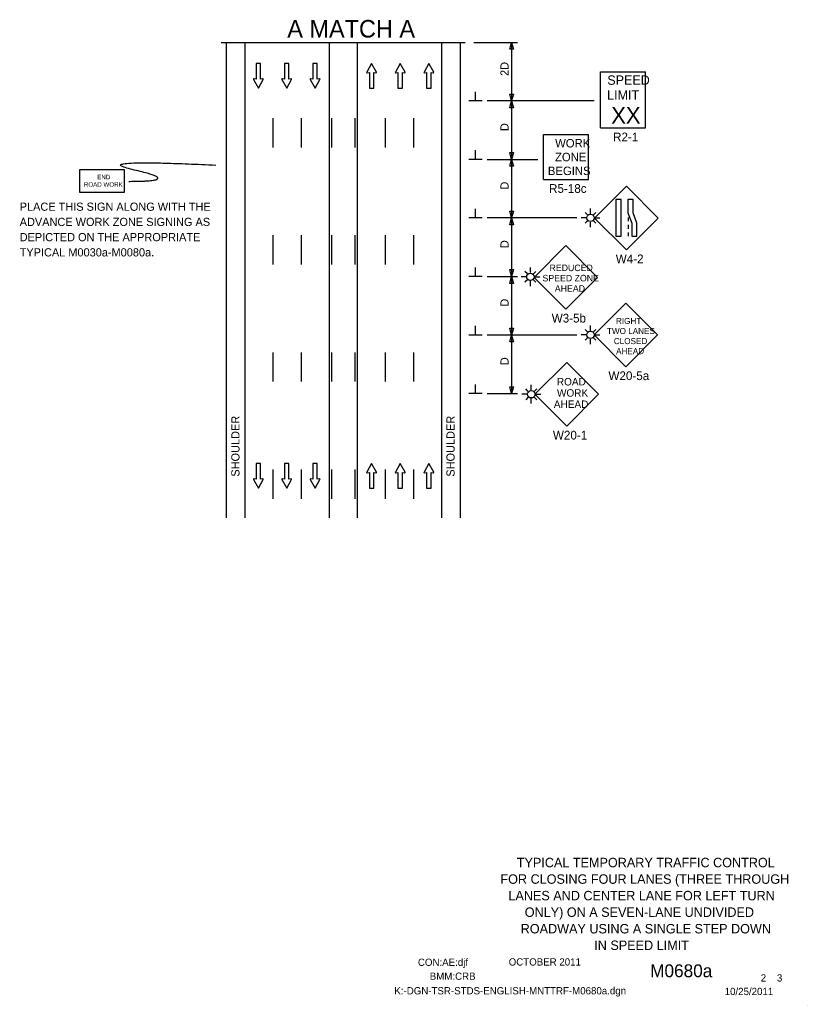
# Model space of a CAD drawing. Extents: x 16038 to 19504, y 5710 to 8321.
# Drawn here: x 17779 to 18453, y 5924 to 6766 of the extents above; entities that cross this region are included whole.
import ezdxf

# ---------------------------------------------------------------- set-up
doc = ezdxf.new("R2010")
doc.units = 0
for name, color, linetype in [('ALI_LEGAL_EX', 7, 'Continuous'), ('BORDER', 7, 'Continuous'), ('BORDER_SIGNAL_WO', 7, 'Continuous'), ('MT_SCRATCH_LEVEL_E', 7, 'Continuous'), ('PAVT_EDGE_EX', 7, 'Continuous'), ('TRAFFIC_SIGNS_PR', 7, 'Continuous'), ('TYPICAL_TEXT_DIMEN_PR', 7, 'Continuous')]:
    doc.layers.add(name, color=color, linetype=linetype)

msp = doc.modelspace()

# ---------------------------------------------------------------- linework, layer by layer
at = {"layer": 'ALI_LEGAL_EX'}
for points in [[(17995.77, 6682.18), (17995.77, 6657.18)], [(18019.77, 6682.18), (18019.77, 6657.18)], [(18045.77, 6682.18), (18045.77, 6657.18)], [(18065.77, 6682.18), (18065.77, 6657.18)], [(18091.77, 6682.18), (18091.77, 6657.18)], [(18115.77, 6682.18), (18115.77, 6657.18)], [(17995.77, 6582.18), (17995.77, 6557.18)], [(18019.77, 6582.18), (18019.77, 6557.18)], [(18045.77, 6582.18), (18045.77, 6557.18)], [(18065.77, 6582.18), (18065.77, 6557.18)], [(18091.77, 6582.18), (18091.77, 6557.18)], [(18115.77, 6582.18), (18115.77, 6557.18)], [(17995.77, 6482.18), (17995.77, 6457.18)], [(18019.77, 6482.18), (18019.77, 6457.18)], [(18045.77, 6482.18), (18045.77, 6457.18)], [(18065.77, 6482.18), (18065.77, 6457.18)], [(18091.77, 6482.18), (18091.77, 6457.18)], [(18115.77, 6482.18), (18115.77, 6457.18)], [(17995.77, 6382.18), (17995.77, 6357.18)], [(18019.77, 6382.18), (18019.77, 6357.18)], [(18045.77, 6382.18), (18045.77, 6357.18)], [(18065.77, 6382.18), (18065.77, 6357.18)], [(18091.77, 6382.18), (18091.77, 6357.18)], [(18115.77, 6382.18), (18115.77, 6357.18)]]:
    msp.add_lwpolyline(points, dxfattribs=at)
at = {"layer": 'BORDER'}
for p, q in [((18318.25, 6011.25), (18318.25, 6011.25)), ((18452.55, 5924.4), (18452.55, 5924.4))]:
    msp.add_line(p, q, dxfattribs=at)
at = {"layer": 'MT_SCRATCH_LEVEL_E'}
for p, q in [((17985.18, 6728.89), (17981.44, 6728.89)), ((17981.44, 6728.89), (17981.44, 6715.63)), ((17985.18, 6728.89), (17981.44, 6728.89)), ((17981.44, 6728.89), (17981.44, 6715.63)), ((17985.18, 6715.63), (17985.18, 6728.89)), ((17985.18, 6715.63), (17985.18, 6728.89)), ((18009.44, 6728.89), (18005.69, 6728.89)), ((18005.69, 6728.89), (18005.69, 6715.63)), ((18009.44, 6728.89), (18005.69, 6728.89)), ((18005.69, 6728.89), (18005.69, 6715.63)), ((18009.44, 6715.63), (18009.44, 6728.89)), ((18009.44, 6715.63), (18009.44, 6728.89)), ((18033.69, 6728.89), (18029.95, 6728.89)), ((18029.95, 6728.89), (18029.95, 6715.63)), ((18033.69, 6728.89), (18029.95, 6728.89)), ((18029.95, 6728.89), (18029.95, 6715.63)), ((18033.69, 6715.63), (18033.69, 6728.89)), ((18033.69, 6715.63), (18033.69, 6728.89)), ((18080.01, 6728.89), (18075.9, 6721.65)), ((18080.01, 6728.89), (18075.9, 6721.65)), ((18084.16, 6721.65), (18080.01, 6728.89)), ((18084.16, 6721.65), (18080.01, 6728.89)), ((18104.51, 6728.89), (18100.4, 6721.65)), ((18104.51, 6728.89), (18100.4, 6721.65)), ((18108.65, 6721.65), (18104.51, 6728.89)), ((18108.65, 6721.65), (18104.51, 6728.89)), ((18129, 6728.89), (18124.89, 6721.65)), ((18129, 6728.89), (18124.89, 6721.65)), ((18133.15, 6721.65), (18129, 6728.89)), ((18133.15, 6721.65), (18129, 6728.89)), ((18076.38, 6720.96), (18078.16, 6721.28)), ((18076.38, 6720.96), (18078.16, 6721.28)), ((18078.16, 6721.28), (18078.16, 6708.02)), ((18078.16, 6721.28), (18078.16, 6708.02)), ((18081.9, 6708.02), (18081.9, 6721.28)), ((18081.9, 6721.28), (18083.68, 6720.96)), ((18081.9, 6708.02), (18081.9, 6721.28)), ((18081.9, 6721.28), (18083.68, 6720.96)), ((18100.88, 6720.96), (18102.65, 6721.28)), ((18100.88, 6720.96), (18102.65, 6721.28)), ((18102.65, 6721.28), (18102.65, 6708.02)), ((18102.65, 6721.28), (18102.65, 6708.02)), ((18106.4, 6708.02), (18106.4, 6721.28)), ((18106.4, 6721.28), (18108.17, 6720.96)), ((18106.4, 6708.02), (18106.4, 6721.28)), ((18106.4, 6721.28), (18108.17, 6720.96)), ((18125.37, 6720.96), (18127.15, 6721.28)), ((18125.37, 6720.96), (18127.15, 6721.28)), ((18127.15, 6721.28), (18127.15, 6708.02)), ((18127.15, 6721.28), (18127.15, 6708.02)), ((18130.89, 6708.02), (18130.89, 6721.28)), ((18130.89, 6721.28), (18132.67, 6720.96)), ((18130.89, 6708.02), (18130.89, 6721.28)), ((18130.89, 6721.28), (18132.67, 6720.96)), ((17979.18, 6715.26), (17983.33, 6708.02)), ((17979.18, 6715.26), (17983.33, 6708.02)), ((17981.44, 6715.63), (17979.66, 6715.95)), ((17981.44, 6715.63), (17979.66, 6715.95)), ((17983.33, 6708.02), (17987.44, 6715.26)), ((17983.33, 6708.02), (17987.44, 6715.26)), ((17986.96, 6715.95), (17985.18, 6715.63)), ((17986.96, 6715.95), (17985.18, 6715.63)), ((18003.44, 6715.26), (18007.58, 6708.02)), ((18003.44, 6715.26), (18007.58, 6708.02)), ((18005.69, 6715.63), (18003.92, 6715.95)), ((18005.69, 6715.63), (18003.92, 6715.95)), ((18007.58, 6708.02), (18011.69, 6715.26)), ((18007.58, 6708.02), (18011.69, 6715.26)), ((18011.21, 6715.95), (18009.44, 6715.63)), ((18011.21, 6715.95), (18009.44, 6715.63)), ((18027.69, 6715.26), (18031.84, 6708.02)), ((18027.69, 6715.26), (18031.84, 6708.02)), ((18029.95, 6715.63), (18028.17, 6715.95)), ((18029.95, 6715.63), (18028.17, 6715.95)), ((18031.84, 6708.02), (18035.95, 6715.26)), ((18031.84, 6708.02), (18035.95, 6715.26)), ((18035.47, 6715.95), (18033.69, 6715.63)), ((18035.47, 6715.95), (18033.69, 6715.63)), ((18078.16, 6708.02), (18081.9, 6708.02)), ((18078.16, 6708.02), (18081.9, 6708.02)), ((18102.65, 6708.02), (18106.4, 6708.02)), ((18102.65, 6708.02), (18106.4, 6708.02)), ((18127.15, 6708.02), (18130.89, 6708.02)), ((18127.15, 6708.02), (18130.89, 6708.02)), ((17985.18, 6387.14), (17981.44, 6387.14)), ((17981.44, 6387.14), (17981.44, 6373.88)), ((17985.18, 6387.14), (17981.44, 6387.14)), ((17981.44, 6387.14), (17981.44, 6373.88)), ((17985.18, 6373.88), (17985.18, 6387.14)), ((17985.18, 6373.88), (17985.18, 6387.14)), ((18009.44, 6387.14), (18005.69, 6387.14)), ((18005.69, 6387.14), (18005.69, 6373.88)), ((18009.44, 6387.14), (18005.69, 6387.14)), ((18005.69, 6387.14), (18005.69, 6373.88)), ((18009.44, 6373.88), (18009.44, 6387.14)), ((18009.44, 6373.88), (18009.44, 6387.14)), ((18033.69, 6387.14), (18029.95, 6387.14)), ((18029.95, 6387.14), (18029.95, 6373.88)), ((18033.69, 6387.14), (18029.95, 6387.14)), ((18029.95, 6387.14), (18029.95, 6373.88)), ((18033.69, 6373.88), (18033.69, 6387.14)), ((18033.69, 6373.88), (18033.69, 6387.14)), ((18080.01, 6387.14), (18075.9, 6379.9)), ((18080.01, 6387.14), (18075.9, 6379.9)), ((18084.16, 6379.9), (18080.01, 6387.14)), ((18084.16, 6379.9), (18080.01, 6387.14)), ((18104.51, 6387.14), (18100.4, 6379.9)), ((18104.51, 6387.14), (18100.4, 6379.9)), ((18108.65, 6379.9), (18104.51, 6387.14)), ((18108.65, 6379.9), (18104.51, 6387.14)), ((18129, 6387.14), (18124.89, 6379.9)), ((18129, 6387.14), (18124.89, 6379.9)), ((18133.15, 6379.9), (18129, 6387.14)), ((18133.15, 6379.9), (18129, 6387.14)), ((17981.44, 6373.88), (17979.66, 6374.2)), ((17981.44, 6373.88), (17979.66, 6374.2)), ((17986.96, 6374.2), (17985.18, 6373.88)), ((17986.96, 6374.2), (17985.18, 6373.88)), ((18005.69, 6373.88), (18003.92, 6374.2)), ((18005.69, 6373.88), (18003.92, 6374.2)), ((18011.21, 6374.2), (18009.44, 6373.88)), ((18011.21, 6374.2), (18009.44, 6373.88)), ((18029.95, 6373.88), (18028.17, 6374.2)), ((18029.95, 6373.88), (18028.17, 6374.2)), ((18035.47, 6374.2), (18033.69, 6373.88)), ((18035.47, 6374.2), (18033.69, 6373.88)), ((18076.38, 6379.22), (18078.16, 6379.53)), ((18076.38, 6379.22), (18078.16, 6379.53)), ((18078.16, 6379.53), (18078.16, 6366.27)), ((18078.16, 6379.53), (18078.16, 6366.27)), ((18081.9, 6366.27), (18081.9, 6379.53)), ((18081.9, 6379.53), (18083.68, 6379.22)), ((18081.9, 6366.27), (18081.9, 6379.53)), ((18081.9, 6379.53), (18083.68, 6379.22)), ((18100.88, 6379.22), (18102.65, 6379.53)), ((18100.88, 6379.22), (18102.65, 6379.53)), ((18102.65, 6379.53), (18102.65, 6366.27)), ((18102.65, 6379.53), (18102.65, 6366.27)), ((18106.4, 6366.27), (18106.4, 6379.53)), ((18106.4, 6379.53), (18108.17, 6379.22)), ((18106.4, 6366.27), (18106.4, 6379.53)), ((18106.4, 6379.53), (18108.17, 6379.22)), ((18125.37, 6379.22), (18127.15, 6379.53)), ((18125.37, 6379.22), (18127.15, 6379.53)), ((18127.15, 6379.53), (18127.15, 6366.27)), ((18127.15, 6379.53), (18127.15, 6366.27)), ((18130.89, 6366.27), (18130.89, 6379.53)), ((18130.89, 6379.53), (18132.67, 6379.22)), ((18130.89, 6366.27), (18130.89, 6379.53)), ((18130.89, 6379.53), (18132.67, 6379.22)), ((17979.18, 6373.51), (17983.33, 6366.27)), ((17979.18, 6373.51), (17983.33, 6366.27)), ((17983.33, 6366.27), (17987.44, 6373.51)), ((17983.33, 6366.27), (17987.44, 6373.51)), ((18003.44, 6373.51), (18007.58, 6366.27)), ((18003.44, 6373.51), (18007.58, 6366.27)), ((18007.58, 6366.27), (18011.69, 6373.51)), ((18007.58, 6366.27), (18011.69, 6373.51)), ((18027.69, 6373.51), (18031.84, 6366.27)), ((18027.69, 6373.51), (18031.84, 6366.27)), ((18031.84, 6366.27), (18035.95, 6373.51)), ((18031.84, 6366.27), (18035.95, 6373.51)), ((18078.16, 6366.27), (18081.9, 6366.27)), ((18078.16, 6366.27), (18081.9, 6366.27)), ((18102.65, 6366.27), (18106.4, 6366.27)), ((18102.65, 6366.27), (18106.4, 6366.27)), ((18127.15, 6366.27), (18130.89, 6366.27)), ((18127.15, 6366.27), (18130.89, 6366.27))]:
    msp.add_line(p, q, dxfattribs=at)
for centre, start, end in [((18076.31, 6721.42), 150.42484, 279.96381), ((18076.31, 6721.42), 150.42484, 279.96381), ((18083.75, 6721.42), 260.03619, 29.77312), ((18083.75, 6721.42), 260.03619, 29.77312), ((18100.8, 6721.42), 150.42484, 279.96381), ((18100.8, 6721.42), 150.42484, 279.96381), ((18108.24, 6721.42), 260.03619, 29.77312), ((18108.24, 6721.42), 260.03619, 29.77312), ((18125.3, 6721.42), 150.42484, 279.96381), ((18125.3, 6721.42), 150.42484, 279.96381), ((18132.74, 6721.42), 260.03619, 29.77312), ((18132.74, 6721.42), 260.03619, 29.77312), ((17979.59, 6715.49), 80.03619, 209.77312), ((17979.59, 6715.49), 80.03619, 209.77312), ((17987.03, 6715.49), 330.42484, 99.96381), ((17987.03, 6715.49), 330.42484, 99.96381), ((18003.85, 6715.49), 80.03619, 209.77312), ((18003.85, 6715.49), 80.03619, 209.77312), ((18011.29, 6715.49), 330.42484, 99.96381), ((18011.29, 6715.49), 330.42484, 99.96381), ((18028.1, 6715.49), 80.03619, 209.77312), ((18028.1, 6715.49), 80.03619, 209.77312), ((18035.54, 6715.49), 330.42484, 99.96381), ((18035.54, 6715.49), 330.42484, 99.96381), ((17979.59, 6373.74), 80.03619, 209.77312), ((17979.59, 6373.74), 80.03619, 209.77312), ((17987.03, 6373.74), 330.42484, 99.96381), ((17987.03, 6373.74), 330.42484, 99.96381), ((18003.85, 6373.74), 80.03619, 209.77312), ((18003.85, 6373.74), 80.03619, 209.77312), ((18011.29, 6373.74), 330.42484, 99.96381), ((18011.29, 6373.74), 330.42484, 99.96381), ((18028.1, 6373.74), 80.03619, 209.77312), ((18028.1, 6373.74), 80.03619, 209.77312), ((18035.54, 6373.74), 330.42484, 99.96381), ((18035.54, 6373.74), 330.42484, 99.96381), ((18076.31, 6379.67), 150.42484, 279.96381), ((18076.31, 6379.67), 150.42484, 279.96381), ((18083.75, 6379.67), 260.03619, 29.77312), ((18083.75, 6379.67), 260.03619, 29.77312), ((18100.8, 6379.67), 150.42484, 279.96381), ((18100.8, 6379.67), 150.42484, 279.96381), ((18108.24, 6379.67), 260.03619, 29.77312), ((18108.24, 6379.67), 260.03619, 29.77312), ((18125.3, 6379.67), 150.42484, 279.96381), ((18125.3, 6379.67), 150.42484, 279.96381), ((18132.74, 6379.67), 260.03619, 29.77312), ((18132.74, 6379.67), 260.03619, 29.77312)]:
    msp.add_arc(centre, 0.463, start, end, dxfattribs=at)
at = {"layer": 'PAVT_EDGE_EX'}
for p, q in [((17955.77, 6747.01), (17955.77, 6340.84)), ((17971.77, 6747.01), (17971.77, 6340.84)), ((18043.77, 6747.01), (18043.77, 6340.84)), ((18067.77, 6747.01), (18067.77, 6340.84)), ((18139.77, 6747.01), (18139.77, 6340.84)), ((18155.77, 6747.01), (18155.77, 6340.84))]:
    msp.add_line(p, q, dxfattribs=at)
at = {"layer": 'TRAFFIC_SIGNS_PR'}
for p, q in [((18275.83, 6721.93), (18314.23, 6721.93)), ((18275.83, 6673.93), (18275.83, 6721.93)), ((18314.23, 6673.93), (18314.23, 6721.93)), ((18275.83, 6673.93), (18314.23, 6673.93)), ((18226.99, 6629.9), (18226.99, 6668.3)), ((18226.99, 6668.3), (18265.39, 6668.3)), ((18265.39, 6629.9), (18265.39, 6668.3)), ((18226.99, 6629.9), (18265.39, 6629.9)), ((18297.85, 6624.09), (18270.69, 6596.94)), ((18325, 6596.94), (18297.85, 6624.09)), ((18264.62, 6599.58), (18262.52, 6601.69)), ((18267.14, 6600.62), (18267.14, 6605.12)), ((18269.65, 6599.58), (18271.76, 6601.69)), ((18263.98, 6597.06), (18259.15, 6597.06)), ((18264.62, 6594.55), (18262.52, 6592.44)), ((18267.14, 6589.1), (18267.14, 6593.51)), ((18269.65, 6594.55), (18271.76, 6592.44)), ((18270.29, 6597.06), (18275.17, 6597.06)), ((18270.69, 6596.94), (18297.85, 6569.78)), ((18297.85, 6569.78), (18325, 6596.94)), ((18299.49, 6597.43), (18299.49, 6594.23)), ((18299.49, 6591.03), (18299.49, 6587.83)), ((18299.49, 6584.63), (18299.49, 6581.43)), ((18246.11, 6573.44), (18218.96, 6546.29)), ((18273.26, 6546.29), (18246.11, 6573.44)), ((18213.32, 6549.27), (18211.21, 6551.37)), ((18215.83, 6550.31), (18215.83, 6554.81)), ((18218.35, 6549.27), (18220.45, 6551.37)), ((18212.68, 6546.75), (18207.84, 6546.75)), ((18213.32, 6544.24), (18211.21, 6542.13)), ((18215.83, 6538.79), (18215.83, 6543.2)), ((18218.35, 6544.24), (18220.45, 6542.13)), ((18218.96, 6546.29), (18246.11, 6519.13)), ((18218.99, 6546.75), (18223.87, 6546.75)), ((18246.11, 6519.13), (18273.26, 6546.29)), ((18297.44, 6524.24), (18270.29, 6497.09)), ((18324.6, 6497.09), (18297.44, 6524.24)), ((18264.62, 6499.61), (18262.52, 6501.71)), ((18267.14, 6500.65), (18267.14, 6505.15)), ((18269.65, 6499.61), (18271.76, 6501.71)), ((18263.98, 6497.09), (18259.15, 6497.09)), ((18264.62, 6494.58), (18262.52, 6492.47)), ((18267.14, 6489.13), (18267.14, 6493.54)), ((18269.65, 6494.58), (18271.76, 6492.47)), ((18270.29, 6497.09), (18275.17, 6497.09)), ((18270.29, 6497.09), (18297.44, 6469.94)), ((18297.44, 6469.94), (18324.6, 6497.09)), ((18246.93, 6473.55), (18219.74, 6446.37)), ((18274.11, 6446.37), (18246.93, 6473.55)), ((18214.07, 6448.88), (18211.97, 6450.99)), ((18216.59, 6449.92), (18216.59, 6454.42)), ((18219.1, 6448.88), (18221.21, 6450.99)), ((18213.43, 6446.37), (18208.6, 6446.37)), ((18214.07, 6443.86), (18211.97, 6441.75)), ((18216.59, 6438.4), (18216.59, 6442.81)), ((18219.1, 6443.86), (18221.21, 6441.75)), ((18219.74, 6446.37), (18224.62, 6446.37)), ((18219.74, 6446.37), (18246.93, 6419.18)), ((18246.93, 6419.18), (18274.11, 6446.37))]:
    msp.add_line(p, q, dxfattribs=at)
for points in [[(17830.52, 6618.92), (17868.92, 6618.92), (17868.92, 6638.12), (17830.52, 6638.12)], [(18288.95, 6612.67), (18288.95, 6581.43), (18293.44, 6581.43), (18293.44, 6612.67)], [(18299.09, 6612.67), (18299.09, 6601.49), (18302.43, 6592.61), (18302.43, 6581.43), (18306.92, 6581.43), (18306.92, 6592.61), (18303.58, 6601.49), (18303.58, 6612.67)]]:
    msp.add_lwpolyline(points, close=True, dxfattribs=at)
for centre in [(18267.14, 6597.06), (18215.83, 6546.75), (18267.14, 6497.09), (18216.59, 6446.37)]:
    msp.add_circle(centre, 3.15, dxfattribs=at)
msp.add_open_spline([(17872.52, 6628.3), (17919.75, 6628.3), (17834.73, 6647.64), (17947.03, 6642.15)], degree=2, dxfattribs=at)
at = {"layer": 'TYPICAL_TEXT_DIMEN_PR'}
for p, q in [((17951.47, 6747.01), (18160.07, 6747.01)), ((18043.77, 6747.01), (18067.77, 6747.01)), ((18167.46, 6747.01), (18204.77, 6747.01)), ((18198.2, 6741.15), (18199.77, 6747.01)), ((18199.77, 6747.01), (18201.34, 6741.15)), ((18199.77, 6747.01), (18199.77, 6697.01)), ((18199.77, 6741.15), (18198.2, 6741.15)), ((18201.34, 6741.15), (18199.77, 6741.15)), ((18168.89, 6697.01), (18168.89, 6704.79)), ((18199.77, 6697.01), (18198.2, 6702.87)), ((18198.2, 6702.87), (18199.77, 6702.87)), ((18199.77, 6702.87), (18201.34, 6702.87)), ((18201.34, 6702.87), (18199.77, 6697.01)), ((18174.52, 6697.01), (18163.27, 6697.01)), ((18270.46, 6697.01), (18178.77, 6697.01)), ((18198.2, 6691.15), (18199.77, 6697.01)), ((18199.77, 6697.01), (18201.34, 6691.15)), ((18199.77, 6697.01), (18199.77, 6647.01)), ((18199.77, 6691.15), (18198.2, 6691.15)), ((18201.34, 6691.15), (18199.77, 6691.15)), ((18168.89, 6647.01), (18168.89, 6654.79)), ((18199.77, 6647.01), (18198.2, 6652.87)), ((18198.2, 6652.87), (18199.77, 6652.87)), ((18199.77, 6652.87), (18201.34, 6652.87)), ((18201.34, 6652.87), (18199.77, 6647.01)), ((18174.52, 6647.01), (18163.27, 6647.01)), ((18178.77, 6647.01), (18222.27, 6647.01)), ((18198.2, 6641.15), (18199.77, 6647.01)), ((18199.77, 6647.01), (18199.77, 6597.01)), ((18199.77, 6647.01), (18201.34, 6641.15)), ((18199.77, 6641.15), (18198.2, 6641.15)), ((18201.34, 6641.15), (18199.77, 6641.15)), ((18168.89, 6597.01), (18168.89, 6604.79)), ((18199.77, 6597.01), (18198.2, 6602.87)), ((18198.2, 6602.87), (18199.77, 6602.87)), ((18199.77, 6602.87), (18201.34, 6602.87)), ((18201.34, 6602.87), (18199.77, 6597.01)), ((18174.52, 6597.01), (18163.27, 6597.01)), ((18255.57, 6597.01), (18178.77, 6597.01)), ((18198.2, 6591.15), (18199.77, 6597.01)), ((18199.77, 6597.01), (18201.34, 6591.15)), ((18199.77, 6597.01), (18199.77, 6547.01)), ((18199.77, 6591.15), (18198.2, 6591.15)), ((18201.34, 6591.15), (18199.77, 6591.15)), ((18168.89, 6547.01), (18168.89, 6554.79)), ((18199.77, 6547.01), (18198.2, 6552.87)), ((18198.2, 6552.87), (18199.77, 6552.87)), ((18199.77, 6552.87), (18201.34, 6552.87)), ((18201.34, 6552.87), (18199.77, 6547.01)), ((18174.52, 6547.01), (18163.27, 6547.01)), ((18178.77, 6547.01), (18204.77, 6547.01)), ((18198.2, 6541.15), (18199.77, 6547.01)), ((18199.77, 6547.01), (18201.34, 6541.15)), ((18199.77, 6547.01), (18199.77, 6497.01)), ((18199.77, 6541.15), (18198.2, 6541.15)), ((18201.34, 6541.15), (18199.77, 6541.15)), ((18168.89, 6497.01), (18168.89, 6504.79)), ((18199.77, 6497.01), (18198.2, 6502.87)), ((18198.2, 6502.87), (18199.77, 6502.87)), ((18199.77, 6502.87), (18201.34, 6502.87)), ((18201.34, 6502.87), (18199.77, 6497.01)), ((18174.52, 6497.01), (18163.27, 6497.01)), ((18255.57, 6497.01), (18178.77, 6497.01)), ((18198.2, 6491.15), (18199.77, 6497.01)), ((18199.77, 6497.01), (18201.34, 6491.15)), ((18199.77, 6497.01), (18199.77, 6447.01)), ((18199.77, 6491.15), (18198.2, 6491.15)), ((18201.34, 6491.15), (18199.77, 6491.15)), ((18168.89, 6447.01), (18168.89, 6454.79)), ((18199.77, 6447.01), (18198.2, 6452.87)), ((18198.2, 6452.87), (18199.77, 6452.87)), ((18199.77, 6452.87), (18201.34, 6452.87)), ((18201.34, 6452.87), (18199.77, 6447.01)), ((18174.52, 6447.01), (18163.27, 6447.01)), ((18178.77, 6447.01), (18204.77, 6447.01))]:
    msp.add_line(p, q, dxfattribs=at)

# ---------------------------------------------------------------- texts
at = {"layer": 'BORDER'}
for s, p in [('TYPICAL TEMPORARY TRAFFIC CONTROL', (18204.21, 6042.33)), ('FOR CLOSING FOUR LANES (THREE THROUGH', (18190.21, 6028.2)), ('LANES AND CENTER LANE FOR LEFT TURN', (18197.04, 6014.06)), ('ONLY) ON A SEVEN-LANE UNDIVIDED', (18211.02, 5999.92)), ('ROADWAY USING A SINGLE STEP DOWN', (18207.54, 5985.79)), ('IN SPEED LIMIT', (18270.42, 5971.65))]:
    msp.add_text(s, height=8.066, dxfattribs=at).set_placement(p)
at = {"layer": 'BORDER_SIGNAL_WO'}
for s, height, p in [('CON:AE:djf', 6.2, (18119.69, 5958.06)), ('    OCTOBER 2011    ', 6.2, (18188.08, 5958.34)), ('    M0680a   ', 11, (18301.86, 5948.38)), ('BMM:CRB   ', 6.2, (18129.81, 5946.17)), (' 2    3 ', 6.2, (18410.45, 5944.7)), ('K:-DGN-TSR-STDS-ENGLISH-MNTTRF-M0680a.dgn        ', 6.2, (18099.55, 5933.71)), ('10/25/2011    ', 6.2, (18381.93, 5933.13))]:
    msp.add_text(s, height=height, dxfattribs=at).set_placement(p)
at = {"layer": 'TRAFFIC_SIGNS_PR'}
for s, height, p in [('SPEED', 8, (18281.6, 6710.79)), ('LIMIT', 8, (18281.44, 6697.99)), ('XX', 14.031, (18284.94, 6677.68)), ('R2-1', 7.44, (18286.51, 6662.49)), ('WORK', 7.217, (18236.99, 6657.27)), ('ZONE', 7.217, (18236.87, 6645.46)), ('BEGINS', 7.217, (18230.8, 6633.65)), ('ROAD WORK', 3.831, (17834.13, 6623.66)), ('END', 3.831, (17845.53, 6630.05)), ('R5-18c', 7.44, (18231.8, 6618.46)), ('PLACE THIS SIGN ALONG WITH THE', 7, (17779.24, 6603.14)), ('ADVANCE WORK ZONE SIGNING AS', 7, (17779.24, 6590.14)), ('DEPICTED ON THE APPROPRIATE', 7, (17779.24, 6577.14)), ('TYPICAL M0030a-M0080a.', 7, (17779.24, 6564.14)), ('W4-2', 7.44, (18288.8, 6558.34)), ('REDUCED', 5.6, (18232.17, 6551.6)), ('SPEED ZONE', 5.6, (18226.16, 6542.8)), ('AHEAD', 5.6, (18236.72, 6533.99)), ('W3-5b', 7.44, (18234.06, 6507.69)), ('RIGHT', 5.2, (18289.02, 6506.43)), ('TWO LANES', 5.2, (18281.3, 6497.83)), ('CLOSED', 5.2, (18287.15, 6489.23)), ('AHEAD', 5.2, (18289.1, 6480.63)), ('ROAD', 6.408, (18238.46, 6453.91)), ('W20-5a', 7.44, (18282.58, 6458.5)), ('WORK', 6.408, (18238.57, 6444.3)), ('AHEAD', 6.408, (18235.87, 6434.69)), ('W20-1', 7.449, (18235.08, 6407.73))]:
    msp.add_text(s, height=height, dxfattribs=at).set_placement(p)
at = {"layer": 'TYPICAL_TEXT_DIMEN_PR'}
msp.add_text('A MATCH A', height=15, dxfattribs=at).set_placement((18008.01, 6751.15))
for s, p in [('2D', (18197.21, 6718.35)), ('D', (18197.21, 6671.23)), ('D', (18197.21, 6621.23)), ('D', (18197.21, 6571.23)), ('D', (18197.21, 6521.23)), ('D', (18197.21, 6471.23)), ('SHOULDER', (17967.14, 6375.99)), ('SHOULDER', (18151.05, 6375.99))]:
    msp.add_text(s, height=7, rotation=90, dxfattribs=at).set_placement(p)

doc.saveas('drawing.dxf')
